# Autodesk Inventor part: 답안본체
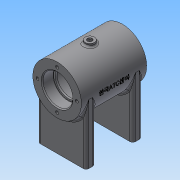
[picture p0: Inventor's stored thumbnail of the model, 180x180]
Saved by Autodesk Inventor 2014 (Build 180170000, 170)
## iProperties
Created: 2020-07
Part Number: 답안본체
Material: 일반
Document SubType Name: Modeling
Designer: net
Density: 1 g/cm^3
Appearance: 기본값
Author: net
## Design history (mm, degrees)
sketch "스케치1"
  geometry: L1 (0, 0)-(70, 0); L2 (0, 0)-(0, 26); L3 (0, 26)-(70, 26); L4 (70, 26)-(70, 0)
  constraints: 8 end point, 2 perpendicular, 1 horizontal, 1 parallel
  dimensions: "d0" = 70 distance of L1.start L1.end; "d1" = 52 diameter of L3 L1
revolve "회전1" sketch "스케치1" stored, may be unused: angle "d2" = 90 deg
sketch "스케치2"
  geometry: L1 (0, -26)-(0, 26) reference; L2 (0, 26)-(70, 26) reference; L3 (70, 26)-(70, -26) reference; L4 (70, -26)-(0, -26) reference; L5 (0, 0)-(70, 0); L6 (0, 0)-(0, 16); L7 (0, 16)-(11.7, 16); L8 (12, 15.7)-(12, 14); L9 (12, 14)-(14, 14); L10 (14, 14)-(14, 18); L11 (17, 21)-(53, 21); L12 (70, 0)-(70, 16); L13 (56, 18)-(56, 14); L14 (56, 14)-(58, 14); L15 (58, 14)-(58, 15.7); L16 (58.3, 16)-(70, 16); A1 r 3 centre (17, 18) between (17, 21) and (14, 18); A2 r 3 centre (53, 18) between (56, 18) and (53, 21); A3 r 0.3 centre (11.7, 15.7) between (12, 15.7) and (11.7, 16); A4 r 0.3 centre (58.3, 15.7) between (58.3, 16) and (58, 15.7); 2 further points
  constraints: 24 end point, 8 point on circle, 8 tangent, 6 perpendicular, 6 point on line, 4 centre point, 3 parallel, 2 equal radius, 1 collinear, 1 midpoint
  dimensions: "d3" = 32 diameter of L7 L5; "d5" = 28 diameter of L9 L5; "d7" = 28 diameter of L14 L5; "d8" = 32 diameter of L16 L5; "d9" = 42 diameter of L11 L5; "d10" = 12 distance of L6.end point (12, 16); "d11" = 12 distance of point (58, 16) L12.end; "d12" = 2 distance of L13.end L14.end; "d13" = 2 distance of L8.end L9.end; "d14" = 3 radius of A1; "d15" = 0.3 radius of A3
revolve "회전2" sketch "스케치2" stored, may be unused: angle "d16" = 90 deg
sketch "스케치3"
  geometry: C1 r 16 at (0, 0) reference; 1 further point
  constraints: 1 vertical alignment
  dimensions: "d17" = 21 distance of C1.centre point (0, 21)
hole "구멍1" sketch "스케치3" at (0, 21) diameter "d18" = 3.242; stored, may be unused: countersink angle "d22" = 90 deg, drill point angle "d24" = 118 deg; dims "d19" = 8, "d20" = 4, "d21" = 2, "d23" = 10
node "작업 평면1"
node "작업 평면2"
sketch "스케치4"
  geometry: C1 r 5 at (0, 35); 1 further point
  constraints: 1 centre point, 1 vertical alignment
  dimensions: "d29" = 10 diameter of C1; "d30" = 35 distance of C1.centre point (0, 0)
extrude "돌출1" join sketch "스케치4" stored distance "d31" = 10; taper "d32" = 0 deg
sketch "스케치5"
  geometry: C1 r 5 at (0, 0) reference; 2 further points
  constraints: 1 coincident
hole "구멍2" sketch "스케치5" at (0, 0) diameter "d33" = 5.188; stored, may be unused: countersink angle "d37" = 90 deg, drill point angle "d39" = 118 deg; dims "d34" = 8, "d35" = 4, "d36" = 2, "d38" = 30
fillet "모깎기1" dims "d40" = 2
node "작업 평면3"
chamfer "모따기1" distance "d63" = 1; stored, may be unused: second distance "d64" = 2, angle "d65" = 45 deg
sketch "스케치9"
  geometry: L1 (2.594, 20.839)-(2.594, 29) reference; L2 (2.594, 29)-(5, 29) reference; L3 (5, 29)-(5, 27.111) reference; L4 (-5, 27.111)-(-5, 29) reference; L5 (-5, 29)-(-2.594, 29) reference; L6 (-2.594, 29)-(-2.594, 20.839) reference; L7 (0, 0)-(0, -6.775); L8 (0, 0)-(-9.919, -27.251); A1 r 21 centre (0, 0) between (-2.594, 20.839) and (2.594, 20.839) reference; A2 r 26 centre (0, 0) between (-6.5, 25.174) and (6.5, 25.174) reference; 1 further point
  constraints: 4 end point, 1 parallel, 2 other
  dimensions: "d70" = 20 deg angle of L8 L7; "d71" = 29 distance of L7.start L8.end
  node "절단 모서리 투영3"
node "작업 평면5"
sketch "스케치10"
  geometry: C1 r 6 at (0, 0); 2 further points
  constraints: 1 centre point, 1 coincident
  dimensions: "d72" = 12 diameter of C1
extrude "돌출2" join sketch "스케치10" stored distance "d73" = 10; taper "d74" = 0 deg
sketch "스케치11"
  geometry: C1 r 6 at (0, 0) reference; 2 further points
  constraints: 1 coincident
hole "구멍4" sketch "스케치11" at (0, 0) diameter "d75" = 5.188; stored, may be unused: countersink angle "d79" = 90 deg, drill point angle "d81" = 118 deg; dims "d76" = 8, "d77" = 4, "d78" = 2, "d80" = 30
fillet "모깎기4" dims "d82" = 2
node "작업 평면7"
sketch "스케치12"
  geometry: L1 (-26, 0)-(-26, -64); L2 (-26, -64)-(26, -64); L3 (26, -64)-(26, 0); C1 r 20.236 at (0, 0) reference; A1 r 26 centre (0, 0) between (-26, 0) and (26, 0) reference; 1 further point
  constraints: 6 end point, 2 point on circle, 1 parallel, 1 perpendicular, 1 tangent, 1 vertical
  dimensions: "d85" = 64 distance of L1.start L1.end; "d86" = 52 distance of L1.end L2.end
feature "리브2" sketch "스케치12" dims "d87" = 1, "d88" = 10, "d89" = 0, "d90" = 0, "d91" = 1, "d92" = 1
sketch "스케치13"
  geometry: L1 (0, 0)-(52, 0) reference; L2 (52, 10)-(0, 10) reference; L3 (26, 0)-(26, 10); 3 further points
  constraints: 2 end point, 2 midpoint
  dimensions: "d93" = 5 distance from line of point (6, 5) L1; "d94" = 5 distance from line of point (46, 5) L1; "d95" = 20 distance from line of L3 point (6, 5); "d96" = 20 distance from line of point (46, 5) L3
hole "구멍5" sketch "스케치13" at (6, 5), (46, 5) diameter "d97" = 4.134; stored, may be unused: countersink angle "d101" = 90 deg, drill point angle "d103" = 118 deg; dims "d98" = 8, "d99" = 4, "d100" = 2, "d102" = 10
fillet "모깎기5" dims "d104" = 3
fillet "모깎기6" dims "d105" = 3
node "작업 평면8"
sketch "스케치14"
  geometry: L1 (-35, -26)-(-35, 26) reference; L2 (-35, 26)-(35, 26) reference; 2 further points
  constraints: 1 other
  dimensions: "d106" = 26 distance from line of point (0, 0) L2; "d107" = 35 distance from line of point (0, 0) L1
feature "엠보싱2" sketch "스케치14" dims "d0" = 70, "d1" = 52, "d14" = 3, "d108" = 0.5, "d109" = 0
node "솔리드1"
pattern_circular "원형 패턴1" dims angle "d26" = 360 deg
mirror "대칭1"
mirror "대칭3"
node "절단 모서리 투영1"
node "절단 모서리 투영4"
other parameters: "d28" = 29, "d84" = -15
